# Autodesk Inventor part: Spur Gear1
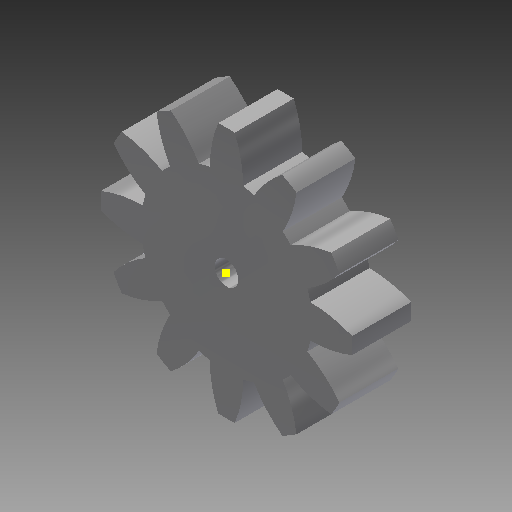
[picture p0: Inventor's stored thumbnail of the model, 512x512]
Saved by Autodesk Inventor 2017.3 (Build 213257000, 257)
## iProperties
Created: 2020-03
Part Number: Spur Gear1
Material: Steel
Document SubType Name: Modeling
Designer: Tim_G
Categories: <?xml version="1.0" encoding="UTF-16"?> <MemberInstance><Categories><FamilyTemplate><FamilyTemplateParameter ValueType="xs:double" Id="1" ObjectReferenceKey="da
Density: 1 g/cm^3
Appearance: Steel
CustomPartVersion: 1
Author: Tim_G
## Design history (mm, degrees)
sketch "Sketch1"
  geometry: C1 r 10.661 at (0, 0)
  constraints: 1 centre point
  dimensions: "d0" = 21.3211 diameter of C1 (= da_da)
extrude "Extrusion1" new body sketch "Sketch1" distance "d1" = 5 (= da_b); taper "d2" = 0 deg
workplane "Work Plane2"
sketch "Sketch2"
  geometry: C1 r 10.661 at (0, 0) reference; C2 r 9.138 at (0, 0)
  constraints: 1 centre point, 1 coincident
  dimensions: "d3" = 18.27523 diameter of C2 (= da_dw)
feature "Pitch Diameter" sketch "Sketch2" dims "d4" = 10, "d5" = 0
workplane "Work Plane8"
workplane "Work Plane9"
feature "Spur Gear" dims "da_b" = 5, "da_d" = 18.27523, "da_aw" = 28.17431, "da_da" = 21.3211, "da_df" = 14.46789, "da_dw" = 18.27523, angle "da_beta" = 0 deg, "da_lefttooth" = 0, "da_righttooth" = 0
sketch "Sketch3"
  geometry: 1 further point
sketch "Sketch4"
  geometry: C1 r 1 at (0, 0); 1 further point
  constraints: 1 centre point, 1 coincident
  dimensions: "d49" = 2 diameter of C1
extrude "Extrusion2" cut sketch "Sketch4" distance "d50" = 5; taper "d51" = 0 deg
body "Solid1"
body "Srf1"
other parameters: "d16" = 28.17431 (= da_aw), "d17" = 0, "d34" = 15 deg (computed from da_z), "d39" = 0, "d41" = 0, "d43" = 28.17431 (= da_aw), "d46" = 28.17431 (= da_aw), "d47" = 0, "d48" = 0
